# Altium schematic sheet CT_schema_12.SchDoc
size 274 x 160 mm
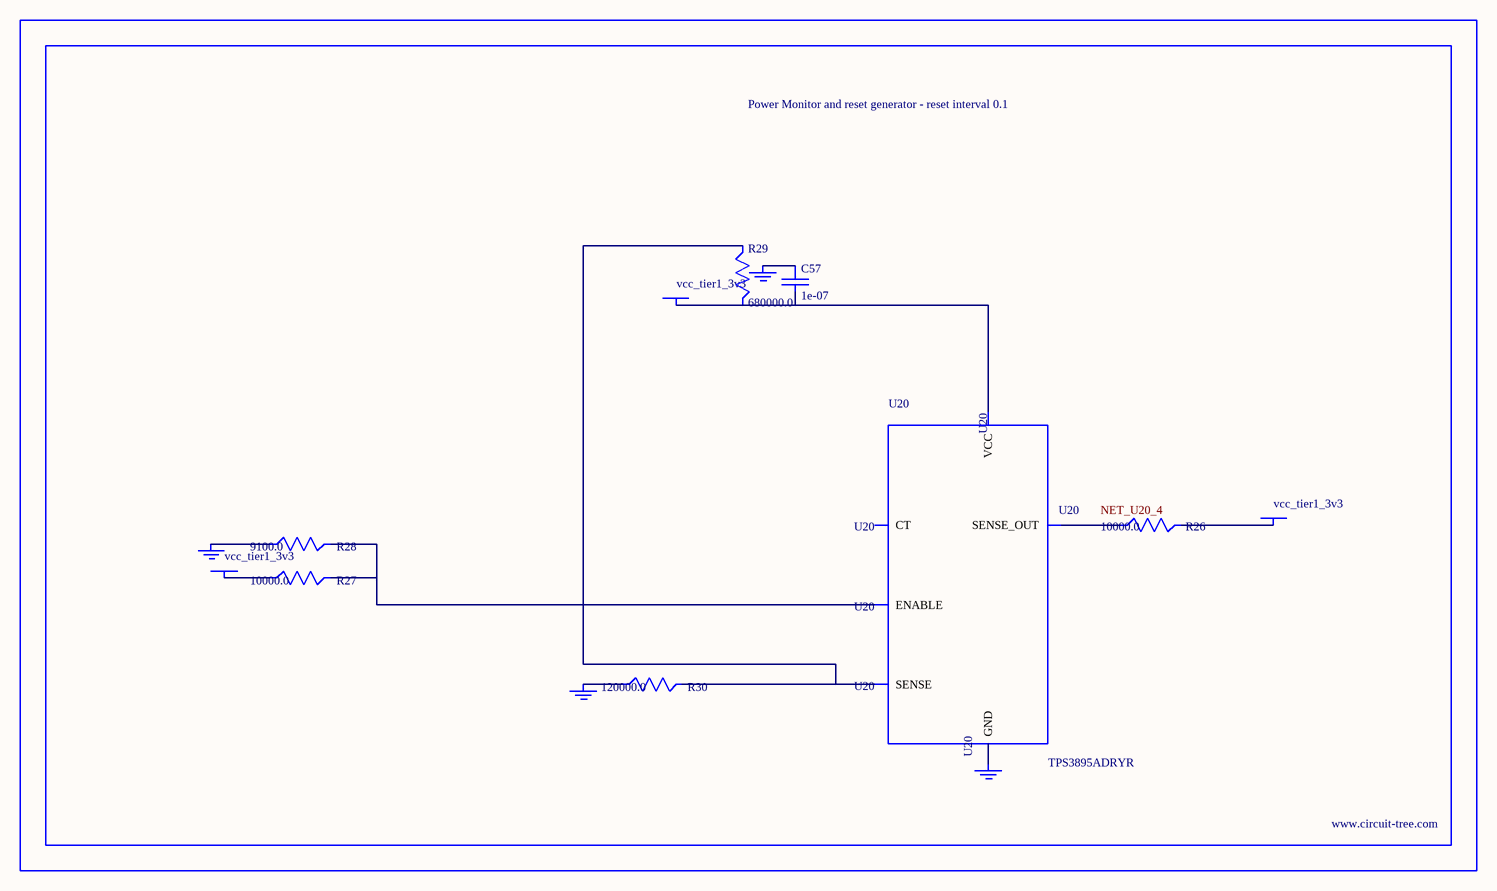
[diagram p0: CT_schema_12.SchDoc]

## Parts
BORDER11  (no value)
C57  1e-07  [C0402]
GND_INSTANCE_11_0  (no value)
GND_INSTANCE_11_1  (no value)
GND_INSTANCE_11_2  (no value)
GND_INSTANCE_11_3  (no value)
POWER_INSTANCE_11_0  vcc_tier1_3v3
POWER_INSTANCE_11_1  vcc_tier1_3v3
POWER_INSTANCE_11_2  vcc_tier1_3v3
R26  10000.0  [R0603]
R27  10000.0  [R0603]
R28  9100.0  [R0603]
R29  680000.0  [R0603]
R30  120000.0  [R0603]
U20  TPS3895ADRYR  [SON-6]

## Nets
NetC57_1: C57.1 GND_INSTANCE_11_2.0(GND)
NetC57_2: C57.2 POWER_INSTANCE_11_2.0(PWR) R29.2 U20.6(VCC)
NetGND_INSTANCE_11_0_0: GND_INSTANCE_11_0.0(GND) R28.1
NetGND_INSTANCE_11_1_0: GND_INSTANCE_11_1.0(GND) R30.1
NetGND_INSTANCE_11_3_0: GND_INSTANCE_11_3.0(GND) U20.2(GND)
NetPOWER_INSTANCE_11_0_0: POWER_INSTANCE_11_0.0(PWR) R27.1
NetPOWER_INSTANCE_11_1_0: POWER_INSTANCE_11_1.0(PWR) R26.2
NetR26_1: R26.1 U20.4(SENSE_OUT)
NetR27_2: R27.2 R28.2 U20.1(ENABLE)
NetR29_1: R29.1 R30.2 U20.3(SENSE)

Not connected (* = marked no-connect by the designer): U20 5(CT)

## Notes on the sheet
- Labels drawn without touching a wire or pin: NET_U20_4

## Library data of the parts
BORDER11 = BORDER_PAGE11
C57 = C0402C104K3RACTU
GND_INSTANCE_11_0-GND_INSTANCE_11_3 = GND
POWER_INSTANCE_11_0-POWER_INSTANCE_11_2 = PWR
R26 R27 = RC0603JR-0710KL
R28 = RC0603JR-079K1L
R29 = RC0603JR-07680KL
R30 = RC0603JR-07120KL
